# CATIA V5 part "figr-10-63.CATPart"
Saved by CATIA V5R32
Part number: Part3
Bounding box of the stored display mesh (mm): x -76.186 to 89.68, y -206 to 106, z -21.666 to 136.547
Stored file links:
  D:\PROJECTS\Project 2022\CATIA V5 6R 2022\Resources\Part Files\c10_catia_v5_6r2022_prt\c10_catia_v5_6r2022_prt\figr-10-63.CATPart
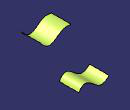
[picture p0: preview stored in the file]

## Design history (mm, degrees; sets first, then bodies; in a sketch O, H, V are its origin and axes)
Set1
  Plane1: type Offset, RefPlane zx-plane, Offset 100, reversed
  Sketch1 on Plane1, origin (0, -100, 0), H (-1, 0, 0), V (0, 0, 1)
    spline S1 through (-89.6797, 128.7958) (-21.8257, 98.6681) (14.6145, 123.4397) (76.1857, 133.4823)
  Extrude1: Element1 Sketch2, Lim1 106, Lim2 0, Direction zx-plane
  Extrude2: Element1 Sketch1, Lim1 106, Lim2 0, Direction Plane1
Body1 (main body)
  Sketch2 on zx-plane, origin (0, 0, 0), H (-1, 0, 0), V (0, 0, 1)
    spline S1 through (-88.2413, 0) (-57.9275, 26.3209) (-11.5211, 3.1904) (32.6399, -21.5353) (74.1811, 0)
    point P1 (-88.2413, 0)
    point P2 (74.1811, 0)
    coincidence: P1 H, P2 H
